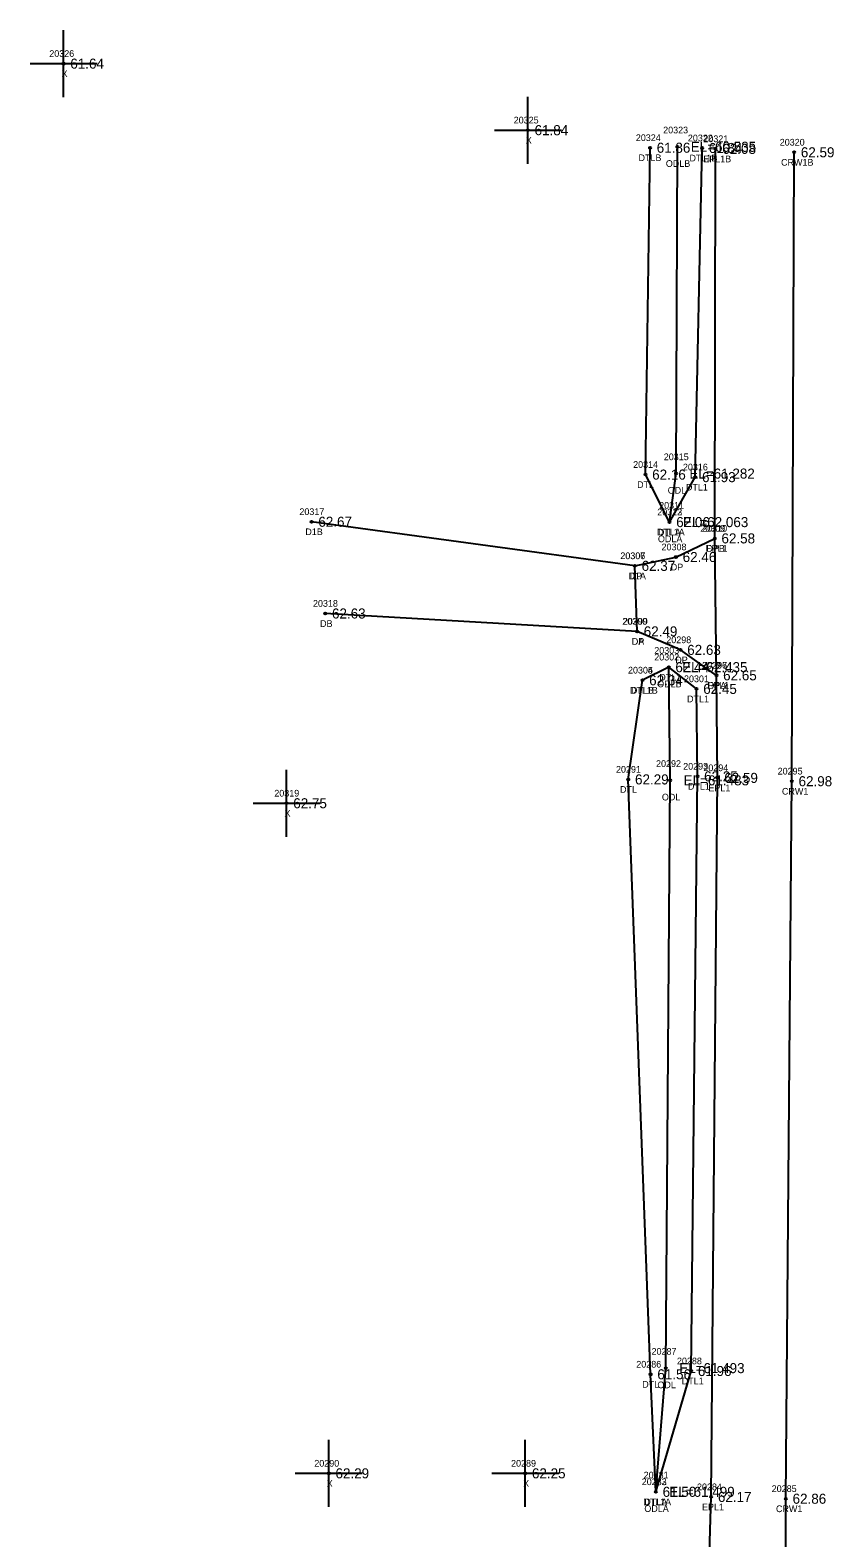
# Model space of a CAD drawing. Extents: x 2420351 to 2422725, y 845330 to 846558.
# Drawn here: x 2420847.1 to 2420967.1, y 845992.1 to 846217.1 of the extents above; entities that cross this region are included whole.
import ezdxf

# ---------------------------------------------------------------- set-up
doc = ezdxf.new("R2010")
doc.units = 0
for name, color, linetype in [('RD_DTM_BkLn1', 7, 'Continuous'), ('RD_EX_Driveway', 7, 'Continuous'), ('RD_EX_Driveway_txCode', 7, 'Continuous'), ('RD_EX_H2O', 7, 'Continuous'), ('RD_EX_H2O_txCode', 7, 'Continuous'), ('RD_EX_Misc', 7, 'Continuous'), ('RD_EX_Misc_txCode', 7, 'Continuous'), ('RD_EX_Road', 7, 'Continuous'), ('RD_EX_Road_txCode', 7, 'Continuous'), ('RD_EX_TX_Driveway_ELEV', 7, 'Continuous'), ('RD_EX_TX_H2O_ELEV', 7, 'Continuous'), ('RD_EX_TX_Misc_ELEV', 7, 'Continuous'), ('RD_EX_TX_Road_ELEV', 7, 'Continuous'), ('RD_HC_Survey_ELEV', 7, 'Continuous'), ('RD_HC_Survey_txCode', 7, 'Continuous'), ('RD_SMD_Locator', 7, 'Continuous')]:
    doc.layers.add(name, color=color, linetype=linetype)

msp = doc.modelspace()

# ---------------------------------------------------------------- linework, layer by layer
at = {"layer": 'RD_DTM_BkLn1'}
msp.add_lwpolyline([(2420953.84, 845715.4), (2420955.91, 845728.49), (2420958.05, 845746.39), (2420959.33, 845767.92), (2420959.83, 845794.17), (2420960.04, 845896.62), (2420959.9, 845997.98), (2420960.79, 846105.06), (2420961.13, 846198.92)], dxfattribs=at)
at = {"layer": 'RD_EX_Driveway'}
for p, q in [((2420937.36, 846137.2), (2420889.11, 846143.78)), ((2420937.68, 846127.42), (2420891.15, 846130.09))]:
    msp.add_line(p, q, dxfattribs=at)
msp.add_lwpolyline([(2420949.53, 846120.86), (2420944.17, 846124.66), (2420937.68, 846127.42), (2420937.36, 846137.2), (2420943.49, 846138.52), (2420949.28, 846141.3)], dxfattribs=at)
at = {"layer": 'RD_EX_H2O'}
for points in [[(2420942.53, 846143.73), (2420938.94, 846150.82), (2420939.62, 846199.6)], [(2420942.53, 846143.73), (2420943.5, 846150.97), (2420943.7, 846199.74)], [(2420942.53, 846143.73), (2420946.38, 846150.44), (2420947.39, 846199.56)], [(2420940.5, 845999.01), (2420939.71, 846016.55), (2420936.38, 846105.33), (2420938.49, 846120.13)], [(2420940.5, 845999.01), (2420945.76, 846017.04), (2420946.69, 846105.79), (2420946.56, 846118.84), (2420942.41, 846122.08), (2420938.49, 846120.13)], [(2420940.5, 845999.01), (2420941.97, 846017.47), (2420942.64, 846105.19), (2420942.41, 846122.08)]]:
    msp.add_lwpolyline(points, dxfattribs=at)
at = {"layer": 'RD_EX_Misc'}
for p, q in [((2420852.09, 846207.15), (2420852.09, 846217.15)), ((2420847.09, 846212.15), (2420857.09, 846212.15)), ((2420921.39, 846197.22), (2420921.39, 846207.22)), ((2420916.39, 846202.22), (2420926.39, 846202.22)), ((2420885.37, 846096.77), (2420885.37, 846106.77)), ((2420880.37, 846101.77), (2420890.37, 846101.77)), ((2420891.67, 845996.77), (2420891.67, 846006.77)), ((2420920.99, 845996.77), (2420920.99, 846006.77)), ((2420886.67, 846001.77), (2420896.67, 846001.77)), ((2420915.99, 846001.77), (2420925.99, 846001.77))]:
    msp.add_line(p, q, dxfattribs=at)
at = {"layer": 'RD_EX_Road'}
msp.add_lwpolyline([(2420911.08, 845716.87), (2420926.22, 845723.04), (2420936.01, 845731.06), (2420942.67, 845742.11), (2420946.54, 845756.04), (2420945.56, 845775.49), (2420946.2, 845794.55), (2420948.14, 845835.31), (2420948.56, 845856.76), (2420948.65, 845897.5), (2420947.59, 845964.03), (2420948.31, 845983.28), (2420948.75, 845998.25), (2420949.7, 846105.56), (2420949.53, 846120.86), (2420949.28, 846141.3), (2420949.41, 846199.43)], dxfattribs=at)
at = {"layer": 'RD_SMD_Locator'}
for centre in [(2420852.09, 846212.15), (2420921.39, 846202.22), (2420939.62, 846199.6), (2420943.7, 846199.74), (2420947.39, 846199.56), (2420949.41, 846199.43), (2420961.13, 846198.92), (2420938.94, 846150.82), (2420943.5, 846150.97), (2420946.38, 846150.44), (2420889.11, 846143.78), (2420942.53, 846143.73), (2420942.53, 846143.73), (2420942.53, 846143.73), (2420949.28, 846141.3), (2420949.28, 846141.3), (2420943.49, 846138.52), (2420937.36, 846137.2), (2420937.36, 846137.2), (2420891.15, 846130.09), (2420937.68, 846127.42), (2420937.68, 846127.42), (2420944.17, 846124.66), (2420938.49, 846120.13), (2420938.49, 846120.13), (2420942.41, 846122.08), (2420942.41, 846122.08), (2420949.53, 846120.86), (2420949.53, 846120.86), (2420946.56, 846118.84), (2420936.38, 846105.33), (2420942.64, 846105.19), (2420946.69, 846105.79), (2420949.7, 846105.56), (2420960.79, 846105.06), (2420885.37, 846101.77), (2420939.71, 846016.55), (2420941.97, 846017.47), (2420945.76, 846017.04), (2420891.67, 846001.77), (2420920.99, 846001.77), (2420940.5, 845999.01), (2420940.5, 845999.01), (2420940.5, 845999.01), (2420948.75, 845998.25), (2420959.9, 845997.98)]:
    msp.add_circle(centre, 0.15, dxfattribs=at)

# ---------------------------------------------------------------- texts
at = {"layer": 'RD_EX_Driveway_txCode'}
for s, p in [('20317', (2420887.28, 846144.78)), ('D1B', (2420888.17, 846141.78)), ('20309', (2420947.13, 846142.3)), ('20308', (2420941.34, 846139.52)), ('20306', (2420935.18, 846138.2)), ('20307', (2420935.2, 846138.2)), ('DPB', (2420948.03, 846139.3)), ('D1A', (2420936.4, 846135.2)), ('DP', (2420936.58, 846135.2)), ('DP', (2420942.71, 846136.52)), ('20318', (2420889.31, 846131.09)), ('DB', (2420890.37, 846128.09)), ('20300', (2420935.49, 846128.42)), ('20299', (2420935.57, 846128.42)), ('DA', (2420936.89, 846125.42)), ('DP', (2420936.91, 846125.42)), ('20298', (2420942.05, 846125.66)), ('DP', (2420943.39, 846122.66)), ('20297', (2420947.41, 846121.86)), ('DPA', (2420948.26, 846118.86))]:
    msp.add_text(s, height=1, dxfattribs=at).set_placement(p)
at = {"layer": 'RD_EX_H2O_txCode'}
for s, p in [('20324', (2420937.5, 846200.6)), ('20323', (2420941.58, 846201.74)), ('20322', (2420945.27, 846200.56)), ('DTLB', (2420937.9, 846197.6)), ('ODLB', (2420941.98, 846196.74)), ('DTL1B', (2420945.51, 846197.56)), ('20315', (2420941.67, 846152.97)), ('20314', (2420937.1, 846151.82)), ('20316', (2420944.53, 846151.44)), ('DTL', (2420937.69, 846148.82)), ('DTL1', (2420944.98, 846148.44)), ('ODL', (2420942.26, 846147.97)), ('20312', (2420940.7, 846144.73)), ('20313', (2420940.7, 846144.73)), ('20311', (2420940.98, 846145.73)), ('DTL1A', (2420940.63, 846141.73)), ('DTLA', (2420940.8, 846141.73)), ('ODLA', (2420940.8, 846140.73)), ('20303', (2420940.25, 846124.08)), ('20302', (2420940.25, 846123.08)), ('20304', (2420936.33, 846121.13)), ('20305', (2420936.33, 846121.13)), ('ODLB', (2420940.69, 846119.08)), ('DTL1', (2420941, 846120.08)), ('20301', (2420944.69, 846119.84)), ('DTL1B', (2420936.61, 846118.13)), ('DTLB', (2420936.77, 846118.13)), ('DTL1', (2420945.15, 846116.84)), ('20291', (2420934.54, 846106.33)), ('20292', (2420940.52, 846107.19)), ('20293', (2420944.57, 846106.79)), ('DTL', (2420935.14, 846103.33)), ('DTL1', (2420945.28, 846103.79)), ('ODL', (2420941.39, 846102.19)), ('20287', (2420939.85, 846019.47)), ('20288', (2420943.64, 846018.04)), ('20286', (2420937.57, 846017.55)), ('DTL', (2420938.46, 846014.55)), ('ODL', (2420940.72, 846014.47)), ('DTL1', (2420944.35, 846015.04)), ('20282', (2420938.38, 846000.01)), ('20283', (2420938.38, 846000.01)), ('20281', (2420938.67, 846001.01)), ('DTL1A', (2420938.6, 845997.01)), ('ODLA', (2420938.77, 845996.01)), ('DTLA', (2420938.77, 845997.01))]:
    msp.add_text(s, height=1, dxfattribs=at).set_placement(p)
at = {"layer": 'RD_EX_Misc_txCode'}
for s, p in [('20326', (2420849.95, 846213.15)), ('X', (2420851.78, 846210.15)), ('20325', (2420919.27, 846203.22)), ('X', (2420921.07, 846200.22)), ('20319', (2420883.54, 846102.77)), ('X', (2420885.06, 846099.77)), ('20290', (2420889.51, 846002.77)), ('20289', (2420918.88, 846002.77)), ('X', (2420891.36, 845999.77)), ('X', (2420920.68, 845999.77))]:
    msp.add_text(s, height=1, dxfattribs=at).set_placement(p)
at = {"layer": 'RD_EX_Road_txCode'}
for s, p in [('20321', (2420947.58, 846200.43)), ('EPL1B', (2420947.57, 846197.43)), ('20310', (2420947.41, 846142.3)), ('EPL1', (2420947.91, 846139.3)), ('20296', (2420947.39, 846121.86)), ('EPL1', (2420948.16, 846118.86)), ('20294', (2420947.58, 846106.56)), ('EPL1', (2420948.33, 846103.56)), ('20284', (2420946.63, 845999.25)), ('EPL1', (2420947.38, 845996.25))]:
    msp.add_text(s, height=1, dxfattribs=at).set_placement(p)
at = {"layer": 'RD_EX_TX_Driveway_ELEV'}
for s, p in [('62.67', (2420890.11, 846143.03)), ('62.58', (2420950.28, 846140.55)), ('62.46', (2420944.49, 846137.77)), ('62.37', (2420938.36, 846136.45)), ('62.37', (2420938.36, 846136.45)), ('62.63', (2420892.15, 846129.34)), ('62.49', (2420938.68, 846126.67)), ('62.49', (2420938.68, 846126.67)), ('62.63', (2420945.17, 846123.91)), ('62.65', (2420950.53, 846120.11))]:
    msp.add_text(s, height=1.5, dxfattribs=at).set_placement(p)
at = {"layer": 'RD_EX_TX_H2O_ELEV'}
for s, p in [('61.86', (2420940.62, 846198.85)), ('EL=60.535', (2420945.7, 846198.99)), ('61.84', (2420948.39, 846198.81)), ('62.16', (2420939.94, 846150.07)), ('EL=61.282', (2420945.5, 846150.22)), ('61.93', (2420947.38, 846149.69)), ('62.06', (2420943.53, 846142.98)), ('62.06', (2420943.53, 846142.98)), ('EL=62.063', (2420944.53, 846142.98)), ('62.44', (2420943.41, 846121.33)), ('EL=62.435', (2420944.41, 846121.33)), ('62.34', (2420939.49, 846119.38)), ('62.34', (2420939.49, 846119.38)), ('62.45', (2420947.56, 846118.09)), ('62.29', (2420937.38, 846104.58)), ('EL=61.483', (2420944.64, 846104.44)), ('62.25', (2420947.69, 846105.04)), ('61.56', (2420940.71, 846015.8)), ('EL=61.493', (2420943.97, 846016.72)), ('61.96', (2420946.76, 846016.29)), ('61.50', (2420941.5, 845998.26)), ('61.50', (2420941.5, 845998.26)), ('EL=61.499', (2420942.5, 845998.26))]:
    msp.add_text(s, height=1.5, dxfattribs=at).set_placement(p)
at = {"layer": 'RD_EX_TX_Misc_ELEV'}
for s, p in [('61.64', (2420853.09, 846211.4)), ('61.84', (2420922.39, 846201.47)), ('62.75', (2420886.37, 846101.02)), ('62.29', (2420892.67, 846001.02)), ('62.25', (2420921.99, 846001.02))]:
    msp.add_text(s, height=1.5, dxfattribs=at).set_placement(p)
at = {"layer": 'RD_EX_TX_Road_ELEV'}
for s, p in [('62.08', (2420950.41, 846198.68)), ('62.58', (2420950.28, 846140.55)), ('62.65', (2420950.53, 846120.11)), ('62.59', (2420950.7, 846104.81)), ('62.17', (2420949.75, 845997.5))]:
    msp.add_text(s, height=1.5, dxfattribs=at).set_placement(p)
at = {"layer": 'RD_HC_Survey_ELEV'}
for s, p in [('62.59', (2420962.13, 846198.17)), ('62.98', (2420961.79, 846104.31)), ('62.86', (2420960.9, 845997.23))]:
    msp.add_text(s, height=1.5, dxfattribs=at).set_placement(p)
at = {"layer": 'RD_HC_Survey_txCode'}
for s, p in [('20320', (2420958.98, 846199.92)), ('CRW1B', (2420959.18, 846196.92)), ('20295', (2420958.67, 846106.06)), ('CRW1', (2420959.31, 846103.06)), ('20285', (2420957.78, 845998.98)), ('CRW1', (2420958.42, 845995.98))]:
    msp.add_text(s, height=1, dxfattribs=at).set_placement(p)

doc.saveas('drawing.dxf')
